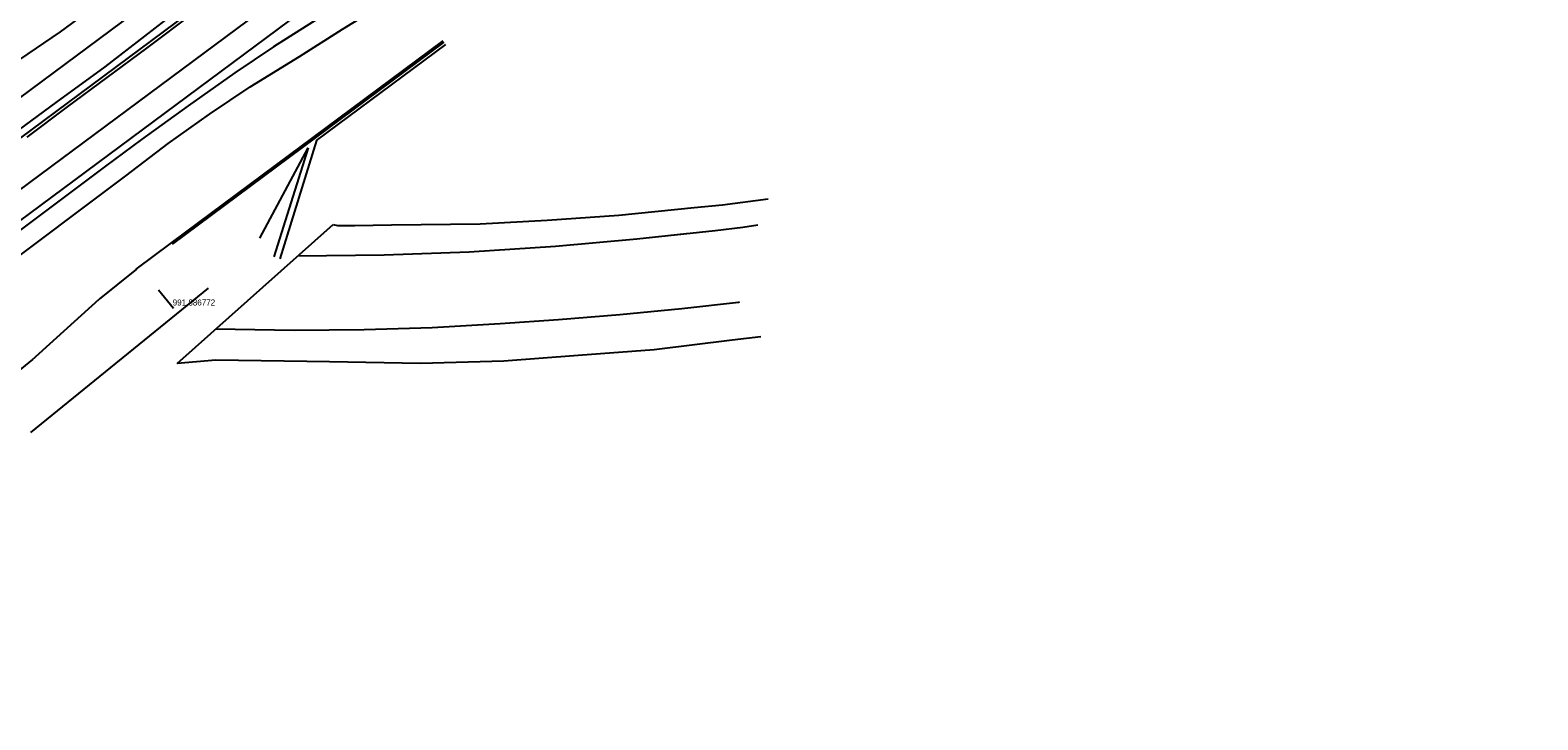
# Model space of a CAD drawing. Extents: x -26 to 1615432, y -20 to 1281970.
# Drawn here: x 1610487 to 1610989, y 1093389 to 1093618 of the extents above; entities that cross this region are included whole.
import ezdxf

# ---------------------------------------------------------------- set-up
doc = ezdxf.new("R2010")
doc.units = 0
for name, color, linetype in [('CLS_Offset_Barr', 7, 'Continuous'), ('CLS_Search_Dist', 7, 'Continuous'), ('CLS_Swell', 7, 'Continuous'), ('Level 5', 7, 'Continuous'), ('RD_EX_Road', 7, 'Continuous'), ('RD_EX_Road_EOT', 7, 'Continuous'), ('RD_HC_Data_Tic', 7, 'Continuous'), ('RD_PD_SuperShp2', 7, 'Continuous'), ('RD_QTY_Surf_Course', 7, 'Continuous'), ('RD_Sketch2', 7, 'Continuous'), ('RD_Sketch6', 7, 'Continuous'), ('RD_XS_NewRW', 7, 'Continuous'), ('RD_XS_OSBase', 7, 'Continuous')]:
    doc.layers.add(name, color=color, linetype=linetype)

msp = doc.modelspace()

# ---------------------------------------------------------------- linework, layer by layer
at = {"layer": 'CLS_Offset_Barr'}
msp.add_line((1610534.26, 1093547.35), (1610624.64, 1093614.53), dxfattribs=at)
at = {"layer": 'CLS_Search_Dist'}
for p, q in [((1609761.27, 1093058.56), (1610880.11, 1093890.25)), ((1610582.53, 1093581.36), (1610625.54, 1093613.33)), ((1610582.53, 1093581.36), (1610570.23, 1093542.05)), ((1610546.43, 1093532.3), (1610487.38, 1093484.2))]:
    msp.add_line(p, q, dxfattribs=at)
at = {"layer": 'CLS_Swell'}
msp.add_line((1610563.66, 1093548.92), (1610579.67, 1093578.92), dxfattribs=at)
at = {"layer": 'Level 5'}
msp.add_line((1610534.91, 1093525.49), (1610529.9, 1093531.64), dxfattribs=at)
at = {"layer": 'RD_EX_Road'}
msp.add_line((1610536.08, 1093507.26), (1610587.98, 1093553.49), dxfattribs=at)
for points in [[(1610430.53, 1093503.27), (1610519.07, 1093569.61), (1610533.1, 1093580.44), (1610546.84, 1093590.17), (1610560.43, 1093599.28), (1610576.8, 1093609.35), (1610591.1, 1093618.44), (1610606.31, 1093627.76), (1610635.77, 1093643.88), (1610642.11, 1093647.23), (1610659.61, 1093655.21), (1610680.2, 1093664), (1610701.53, 1093672.24), (1610723.35, 1093679.91), (1610750.07, 1093687.16), (1610773.56, 1093693.1), (1610794.94, 1093698.46), (1610813.13, 1093703.27), (1610896.56, 1093722.85), (1610919.85, 1093728.3), (1610988.7, 1093743.93)], [(1610513.24, 1093629.39), (1610497.22, 1093617.59), (1610483.73, 1093608.38)], [(1610586.54, 1093624.26), (1610568.16, 1093612.59), (1610555.35, 1093603.88), (1610539.78, 1093592.92), (1610524.25, 1093581.7), (1610512.26, 1093572.86), (1610421.41, 1093504.75)], [(1610481.55, 1093583.48), (1610495.9, 1093594.07), (1610512.22, 1093605.9), (1610525.43, 1093616.12), (1610539.1, 1093626.73)], [(1610541.59, 1093623.89), (1610525.92, 1093612.14), (1610512.73, 1093602.36), (1610499.54, 1093592.57), (1610486.1, 1093582.56)], [(1610587.98, 1093553.49), (1610589.45, 1093553.16), (1610595.25, 1093553.18), (1610607.4, 1093553.32), (1610636.9, 1093553.67), (1610659.21, 1093554.85), (1610683.07, 1093556.52), (1610708.05, 1093559.16), (1610717.49, 1093560.06), (1610732.68, 1093561.96)], [(1610576.28, 1093543.04), (1610604.93, 1093543.37), (1610633.28, 1093544.41), (1610661.99, 1093546.29), (1610689.05, 1093548.74), (1610715.08, 1093551.5), (1610724.32, 1093552.63), (1610729.21, 1093553.3)], [(1610723.18, 1093527.57), (1610722.79, 1093527.52), (1610703.94, 1093525.37), (1610683.36, 1093523.38), (1610662.93, 1093521.75), (1610643.51, 1093520.37), (1610620.97, 1093519.04), (1610598.29, 1093518.38), (1610575.01, 1093518.18), (1610548.9, 1093518.63)], [(1610730.22, 1093516.06), (1610720.69, 1093514.96), (1610694.79, 1093511.74), (1610669.54, 1093509.85), (1610644.75, 1093507.96), (1610617.1, 1093507.19), (1610586.85, 1093507.82), (1610548.98, 1093508.36), (1610536.08, 1093507.26)]]:
    msp.add_lwpolyline(points, dxfattribs=at)
at = {"layer": 'RD_EX_Road_EOT'}
for points in [[(1610586.54, 1093624.26), (1610568.16, 1093612.59), (1610555.35, 1093603.88), (1610539.78, 1093592.92), (1610524.25, 1093581.7), (1610512.26, 1093572.86), (1610421.41, 1093504.75)], [(1610541.59, 1093623.89), (1610525.92, 1093612.14), (1610512.73, 1093602.36), (1610499.54, 1093592.57), (1610486.1, 1093582.56)], [(1610576.28, 1093543.04), (1610604.93, 1093543.37), (1610633.28, 1093544.41), (1610661.99, 1093546.29), (1610689.05, 1093548.74), (1610705.5, 1093550.48)], [(1610723.18, 1093527.57), (1610722.79, 1093527.52), (1610703.94, 1093525.37), (1610683.36, 1093523.38), (1610662.93, 1093521.75), (1610643.51, 1093520.37), (1610620.97, 1093519.04), (1610598.29, 1093518.38), (1610575.01, 1093518.18), (1610548.9, 1093518.63)]]:
    msp.add_lwpolyline(points, dxfattribs=at)
at = {"layer": 'RD_HC_Data_Tic'}
msp.add_line((1610408.65, 1093498.83), (1610907.31, 1093869.51), dxfattribs=at)
at = {"layer": 'RD_PD_SuperShp2'}
for points in [[(1610715.08, 1093682.52), (1610699.43, 1093677.59), (1610696.68, 1093676.64), (1610676.39, 1093669.15), (1610656.39, 1093660.93), (1610654.5, 1093660.11), (1610636.4, 1093651.77), (1610618.65, 1093642.73), (1610601.69, 1093633.39), (1610586.54, 1093624.26), (1610568.16, 1093612.59), (1610555.35, 1093603.88), (1610539.78, 1093592.92), (1610524.25, 1093581.7), (1610512.26, 1093572.86), (1610421.41, 1093504.75)], [(1610541.59, 1093623.89), (1610525.92, 1093612.14), (1610512.73, 1093602.36), (1610499.54, 1093592.57), (1610486.1, 1093582.56)]]:
    msp.add_lwpolyline(points, dxfattribs=at)
at = {"layer": 'RD_QTY_Surf_Course'}
msp.add_line((1609305.59, 1092689.76), (1610698.09, 1093724.15), dxfattribs=at)
at = {"layer": 'RD_Sketch2'}
for p, q in [((1610522.49, 1093538.6), (1610534.26, 1093547.35)), ((1610522.56, 1093538.65), (1610510.19, 1093528.57)), ((1610487.88, 1093508.46), (1610510.19, 1093528.57)), ((1610488.01, 1093508.57), (1610464.76, 1093489.62))]:
    msp.add_line(p, q, dxfattribs=at)
at = {"layer": 'RD_Sketch6'}
msp.add_line((1609767.76, 1093049.83), (1610886.59, 1093881.53), dxfattribs=at)
at = {"layer": 'RD_XS_NewRW'}
msp.add_line((1610579.67, 1093578.92), (1610568.32, 1093542.65), dxfattribs=at)
at = {"layer": 'RD_XS_OSBase'}
msp.add_line((1610534.56, 1093546.94), (1610624.94, 1093614.13), dxfattribs=at)

# ---------------------------------------------------------------- texts
at = {"layer": 'Level 5'}
msp.add_text('991.886772', height=2, dxfattribs=at).set_placement((1610534.65, 1093526.51))

doc.saveas('drawing.dxf')
